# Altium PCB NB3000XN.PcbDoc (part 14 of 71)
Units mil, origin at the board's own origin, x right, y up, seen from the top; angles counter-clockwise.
Board outline 9527.56 x 6929.77 mil, 6 copper layers (Top Layer, GND+SHIELD, MidLayer1, MidLayer2, P2 - 3V3+5V0, Bottom Layer), stack 62.375 mil thick; 832 components, 1027 nets, 4655 pads, 4981 vias.
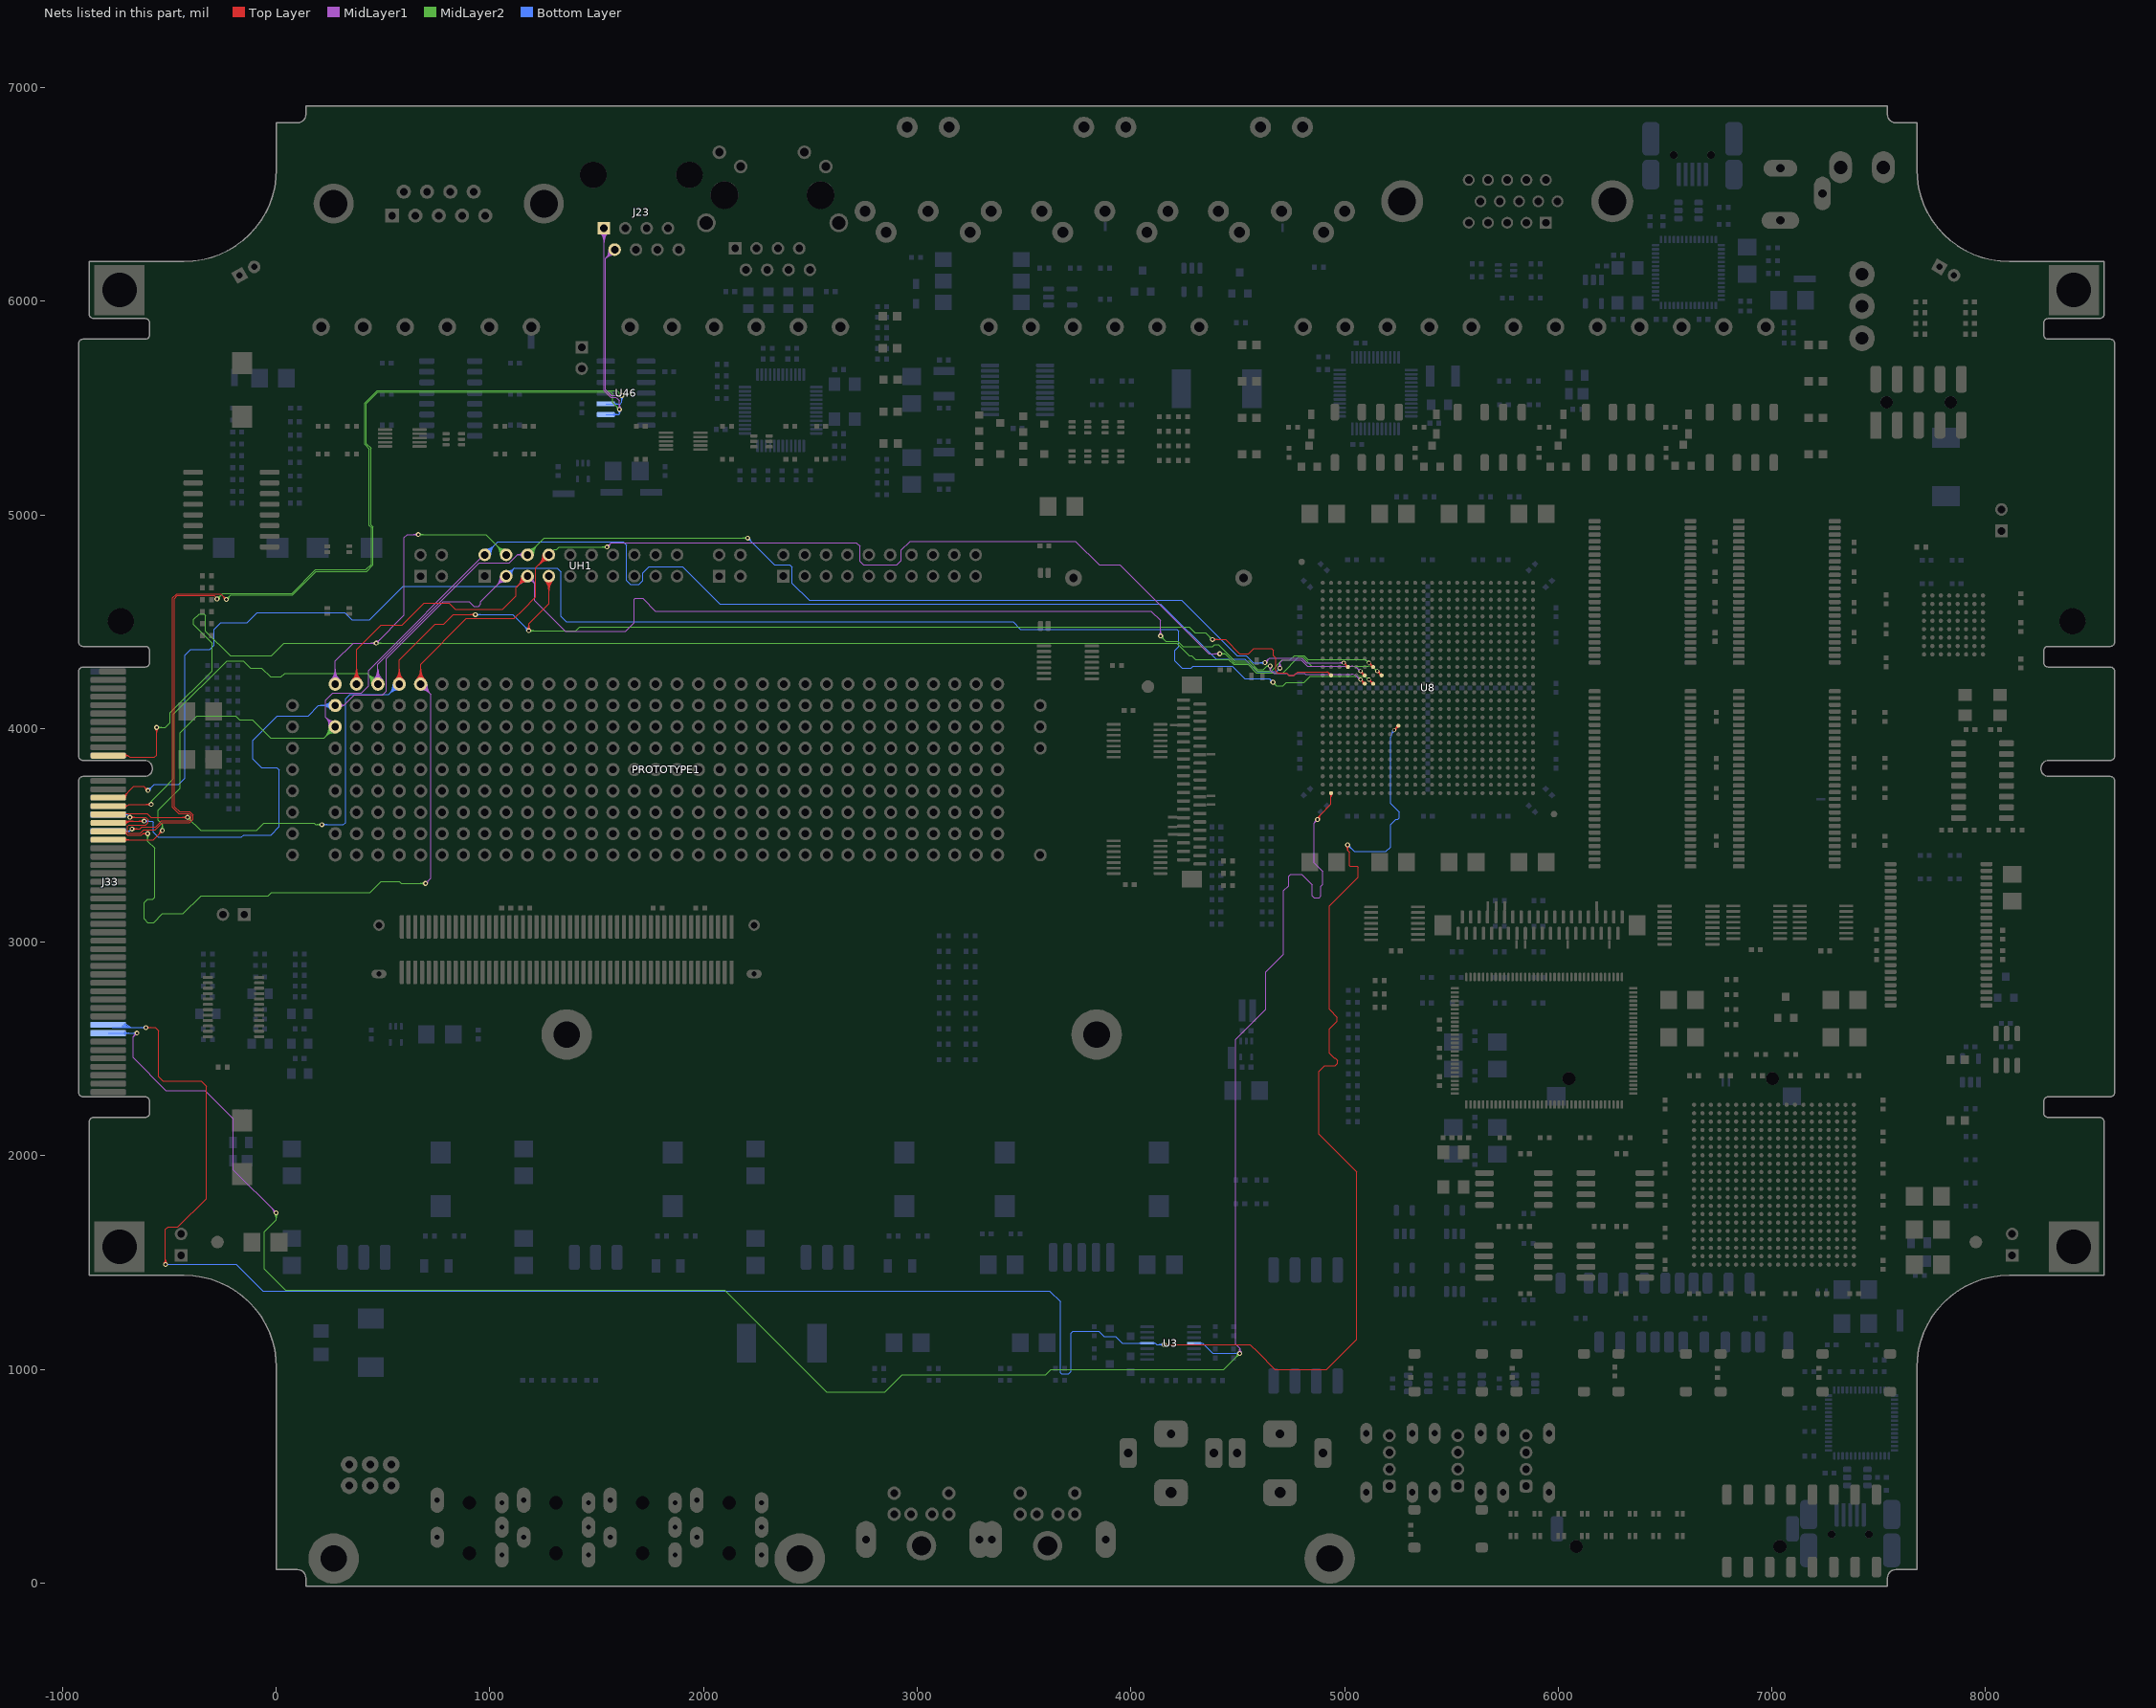
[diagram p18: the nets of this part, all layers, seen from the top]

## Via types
v1: diameter 23, hole 11.81, Top Layer to Bottom Layer, 3672 vias
v2: diameter 26, hole 11.81, Top Layer to Bottom Layer, 461 vias
v3: diameter 19, hole 11.81, Top Layer to Bottom Layer, tented both sides, 396 vias
v4: diameter 23.62, hole 11.81, Top Layer to Bottom Layer, 288 vias
v5: diameter 20, hole 11.81, Top Layer to Bottom Layer, 91 vias
v6: diameter 23, hole 11.81, Top Layer to Bottom Layer, tented both sides, 50 vias
v7: diameter 31, hole 11.81, Top Layer to Bottom Layer, 15 vias
v8: diameter 27.56, hole 11.81, Top Layer to Bottom Layer, tented both sides, 4 vias
v9: diameter 29, hole 11.81, Top Layer to Bottom Layer, 3 vias
v10: diameter 21, hole 11.81, Top Layer to Bottom Layer, 1 vias

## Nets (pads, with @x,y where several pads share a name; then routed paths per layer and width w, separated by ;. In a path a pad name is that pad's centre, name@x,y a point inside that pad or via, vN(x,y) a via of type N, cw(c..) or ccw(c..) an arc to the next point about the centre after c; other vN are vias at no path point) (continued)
ATE.RS485#.TX_N: J23.2 J33.B16 U46.10 | length 6293.5
  Top Layer w4: v4(-685,3585) -611.69,3585 -600.64,3573.96 -600.64,3559.46 -610.89,3549.21 -689.21,3549.21 -695,3543.42 -695,3515 -690,3510 -635,3510 -619.13,3525.87 -566.19,3525.87 -532.56,3559.5 -404.44,3559.5 -389.5,3574.44 -389.5,3595.56 -404.44,3610.5 -452.93,3610.5 -477,3634.57 -477,4607.75 -462.25,4622.5 -290,4622.5 -276.69,4609.19 v4(-276.69,4606.78) ; v4@-680.89,3580.89 cw(c-670.97,3570.97) -670.97,3585 cw(c-670.97,3599.03) v4@-680.89,3589.11 ; v4@-678.06,3578.06 cw(c-661.31,3561.31) -661.31,3585 cw(c-661.31,3608.69) v4@-678.06,3591.94
  MidLayer1 w4: J23.2@1556.57,6239.69 cw(c1506.43,6235.54) 1542,6199.96 ; J23.2@1560.55,6240.02 cw(c1517.7,6236.47) 1548.1,6206.07 cw(c1578.51,6175.66) J23.2@1582.06,6218.51 ; J23.2@1564.54,6240.35 cw(c1528.97,6237.4) 1554.21,6212.17 cw(c1579.44,6186.93) J23.2@1582.39,6222.5 ; J23.2@1568.53,6240.68 cw(c1540.24,6238.34) 1560.31,6218.27 cw(c1580.38,6198.2) J23.2@1582.72,6226.49 ; J23.2@1581.73,6214.53 ccw(c1577.58,6164.39) 1542,6199.96 ; J23.2@1584,6241.96 1542,6199.96 ; v1@1610.81,5552.66 ccw(c1594.59,5536.44) 1594.59,5559.37 ccw(c1594.59,5582.31) v1@1610.81,5566.09 ; v1@1613.64,5555.49 ccw(c1604.25,5546.1) 1604.25,5559.37 ccw(c1604.25,5572.65) v1@1613.64,5563.26 ; v1(1617.52,5559.37) 1568.84,5559.37 1542,5586.21 1542,6199.96
  MidLayer2 w4: v4(-276.69,4606.78) -250.1,4633.37 73.37,4633.37 184,4744 420.06,4744 445.5,4769.44 445.5,4940.56 436,4950.06 436,5309 414.19,5330.81 414.19,5524.19 465.98,5575.98 472.86,5582.86 1594.04,5582.86 v1(1617.52,5559.37) ; v4@-276.69,4612.59 ccw(c-276.69,4626.62) -266.77,4616.7 ccw(c-256.85,4606.78) v4@-270.88,4606.78 ; v4@-276.69,4616.59 ccw(c-276.69,4640.28) -259.94,4623.53 ccw(c-243.19,4606.78) v4@-266.88,4606.78 ; v1@1608.02,5559.37 ccw(c1585.09,5559.37) 1601.31,5575.59 ccw(c1617.52,5591.81) v1@1617.52,5568.87 ; v1@1612.02,5559.37 ccw(c1598.75,5559.37) 1608.14,5568.76 ccw(c1617.52,5578.15) v1@1617.52,5564.87
  Bottom Layer w4: J33.B16@-785.98,3597.74 -697.74,3597.74 ; J33.B16@-706.62,3592.34 cw(c-697.74,3587.75) -697.74,3597.74 ; J33.B16@-706.62,3603.15 ccw(c-697.74,3607.73) -697.74,3597.74 ; v4(-685,3585) -697.74,3597.74 ; U46.10@1542.57,5520.08 1610.08,5520.08 1617.52,5527.52 v1(1617.52,5559.37) ; U46.10@1578.17,5515.97 cw(c1588.09,5506.05) 1588.09,5520.08 cw(c1588.09,5534.11) U46.10@1578.17,5524.19 ; U46.10@1581,5513.14 cw(c1597.75,5496.39) 1597.75,5520.08 cw(c1597.75,5543.76) U46.10@1581,5527.01 ; v1@1610.81,5552.66 cw(c1594.59,5536.44) 1617.52,5536.44 cw(c1640.46,5536.44) v1@1624.24,5552.66 ; v1@1613.64,5555.49 cw(c1604.25,5546.1) 1617.52,5546.1 cw(c1630.8,5546.1) v1@1621.41,5555.49
ATE.RS485#.TX_P: J23.1 J33.B18 U46.9 | length 6345.3
  Top Layer w4: v1(-675,3530) -638.37,3530 -628.37,3540 -563.37,3540 -549.4,3553.98 -535.87,3567.5 -407.75,3567.5 -397.5,3577.75 -397.5,3592.25 -407.75,3602.5 -456.25,3602.5 -485,3631.25 -485,4611.06 -465.02,4631.04 -260.18,4631.04 v1(-233.51,4604.37) ; v1@-671.11,3526.11 cw(c-661.72,3516.72) -661.72,3530 cw(c-661.72,3543.28) v1@-671.11,3533.89 ; v1@-668.28,3523.28 cw(c-652.07,3507.06) -652.07,3530 cw(c-652.07,3552.93) v1@-668.28,3536.72 ; v1@-243.01,4604.37 ccw(c-265.95,4604.37) -249.73,4620.59 ccw(c-233.51,4636.81) v1@-233.51,4613.87 ; v1@-239.01,4604.37 ccw(c-252.29,4604.37) -242.9,4613.76 ccw(c-233.51,4623.15) v1@-233.51,4609.87
  MidLayer1 w4: J23.1@1514.54,6322.5 cw(c1467.54,6275.5) 1534,6275.5 cw(c1600.46,6275.5) J23.1@1553.46,6322.5 ; J23.1@1517.36,6325.32 cw(c1477.2,6285.16) 1534,6285.16 cw(c1590.8,6285.16) J23.1@1550.64,6325.32 ; J23.1@1520.19,6328.15 cw(c1486.86,6294.82) 1534,6294.82 cw(c1581.14,6294.82) J23.1@1547.81,6328.15 ; J23.1@1523.02,6330.98 cw(c1496.51,6304.47) 1534,6304.47 cw(c1571.49,6304.47) J23.1@1544.98,6330.98 ; J23.1@1534,6341.96 1534,5582.9 1565.52,5551.37 1590,5551.37 1606.86,5534.52 v1(1606.86,5494.04) ; v1@1600.14,5500.76 ccw(c1583.92,5516.98) 1606.86,5516.98 ccw(c1629.79,5516.98) v1@1613.57,5500.76 ; v1@1602.97,5497.93 ccw(c1593.58,5507.32) 1606.86,5507.32 ccw(c1620.14,5507.32) v1@1610.75,5497.93
  MidLayer2 w4: v1(-233.51,4604.37) -212.51,4625.37 76.68,4625.37 187.31,4736 423.37,4736 453.5,4766.13 453.5,4943.88 444,4953.38 444,5312.31 422.19,5334.12 422.19,5520.88 476.18,5574.86 1567.14,5574.86 1575,5567 1575,5525.9 v1(1606.86,5494.04) ; v1@-233.51,4609.87 ccw(c-233.51,4623.15) -224.12,4613.76 ccw(c-214.74,4604.37) v1@-228.01,4604.37 ; v1@-233.51,4613.87 ccw(c-233.51,4636.81) -217.3,4620.59 ccw(c-201.08,4604.37) v1@-224.01,4604.37 ; v1@1597.36,5494.04 ccw(c1574.42,5494.04) 1590.64,5510.26 ccw(c1606.86,5526.48) v1@1606.86,5503.54 ; v1@1601.36,5494.04 ccw(c1588.08,5494.04) 1597.47,5503.43 ccw(c1606.86,5512.82) v1@1606.86,5499.54
  Bottom Layer w4: J33.B18@-785.98,3519 -686,3519 v1(-675,3530) ; J33.B18@-711.58,3513.5 cw(c-698.3,3500.22) -698.3,3519 cw(c-698.3,3537.78) J33.B18@-711.58,3524.5 ; J33.B18@-708.76,3510.67 cw(c-688.65,3490.56) -688.65,3519 cw(c-688.65,3547.44) J33.B18@-708.76,3527.33 ; U46.9@1542.57,5470.08 1604.92,5470.08 1606.86,5472.01 ; U46.9@1578.17,5465.97 cw(c1588.09,5456.05) 1588.09,5470.08 cw(c1588.09,5484.11) U46.9@1578.17,5474.19 ; U46.9@1581,5463.14 cw(c1597.75,5446.39) 1597.75,5470.08 cw(c1597.75,5493.76) U46.9@1581,5477.01 ; v1@1600.34,5487.13 cw(c1586.07,5472.01) 1606.86,5472.01 ; v1@1603.08,5490.04 cw(c1594.82,5481.29) 1606.86,5481.29 cw(c1618.89,5481.29) v1@1610.63,5490.04 ; v1(1606.86,5494.04) 1606.86,5472.01 ; v1@1613.38,5487.13 ccw(c1627.64,5472.01) 1606.86,5472.01
ATE.SPDIF.IN: J33.B42 U3.4 U8.AF2 | length 10496.7
  Top Layer w4: v1(4873.52,3574.04) 4873.52,3582.37 4888.15,3597 4888.31,3597 4937.24,3645.93 4937.24,3655.26 4937.24,3660 4937.24,3670 U8.AF2@4937.24,3697.87 ; v1@4874.97,3574.43 cw(c4887.73,3577.89) 4878.38,3587.23 ; v1@4878.83,3575.48 cw(c4895.41,3579.97) 4883.27,3592.12 ; v1@4882.69,3576.53 cw(c4903.09,3582.05) 4888.15,3597 ; U8.AF2@4931.94,3692.57 cw(c4919.14,3679.77) 4937.24,3679.77 cw(c4955.35,3679.77) U8.AF2@4942.55,3692.57 ; U8.AF2@4932.05,3692.68 cw(c4919.52,3680.15) 4937.24,3680.15 cw(c4954.97,3680.15) U8.AF2@4942.44,3692.68
  MidLayer1 w4: v1@-660.98,2575.04 cw(c-683.91,2575.04) -667.69,2558.82 cw(c-651.48,2542.61) v1@-651.48,2565.54 ; v1@-656.98,2575.04 cw(c-670.25,2575.04) -660.86,2565.65 cw(c-651.48,2556.26) v1@-651.48,2569.54 ; v1(-651.48,2575.04) -668.98,2557.54 -668.98,2459.46 -515.73,2306.21 -332.28,2306.21 -200,2173.94 -200,1932.9 v1(-0.48,1733.37) ; v1@-9.98,1733.37 ccw(c-32.91,1733.37) -16.69,1749.59 ccw(c-0.48,1765.81) v1@-0.48,1742.87 ; v1@-5.98,1733.37 ccw(c-19.25,1733.37) -9.86,1742.76 ccw(c-0.48,1752.15) v1@-0.48,1738.87 ; v1@4503.12,1081.76 ccw(c4486.9,1097.98) 4509.84,1097.98 ccw(c4532.77,1097.98) v1@4516.56,1081.76 ; v1@4505.95,1078.93 ccw(c4496.56,1088.32) 4509.84,1088.32 ccw(c4523.12,1088.32) v1@4513.73,1078.93 ; v1(4509.84,1075.04) 4509.84,1098.39 4490.19,1118.04 4490.19,2544.69 4631.86,2686.36 4631.86,2861.36 4715.19,2944.69 4715.19,3240.71 4739.19,3264.71 4739.19,3308.71 4748.52,3318.04 4798.52,3318.04 4848.52,3268.04 4848.52,3216.71 4856.86,3208.37 4881.86,3208.37 4890.19,3216.71 4890.19,3262.04 4898.52,3270.37 4898.52,3331 4857.52,3372 4857.52,3558.04 ; v1@4864.02,3573.95 cw(c4841.83,3573.74) 4857.53,3558.04 ; v1@4868.02,3573.99 cw(c4855.18,3573.86) 4864.26,3564.78 cw(c4873.35,3555.69) v1@4873.47,3568.54 ; v1@4873.43,3564.54 ccw(c4873.22,3542.35) 4857.53,3558.04 ; v1(4873.52,3574.04) 4857.52,3558.04
  MidLayer2 w4: v1@-7.19,1726.66 cw(c-23.41,1710.44) -0.48,1710.44 cw(c22.46,1710.44) v1@6.24,1726.66 ; v1@-4.36,1729.49 cw(c-13.75,1720.1) -0.48,1720.1 cw(c12.8,1720.1) v1@3.41,1729.49 ; v1@-0.85,1733 v1(-0.48,1733.37) -0.48,1700 -55,1645.48 -55,1470.26 43.26,1372 2099.19,1372 2576.19,895 2850,895 2930,975 3601.46,975 3626.5,1000.04 4434.84,1000.04 v1(4509.84,1075.04) ; v1@4500.34,1075.04 cw(c4477.4,1075.04) 4493.62,1058.82 cw(c4509.84,1042.61) v1@4509.84,1065.54 ; v1@4504.34,1075.04 cw(c4491.06,1075.04) 4500.45,1065.65 cw(c4509.84,1056.26) v1@4509.84,1069.54
  Bottom Layer w4: J33.B42@-785.98,2574.12 -668.73,2574.12 -667.81,2575.04 ; J33.B42@-711.58,2568.62 cw(c-698.3,2555.34) -698.3,2574.12 cw(c-698.3,2592.9) J33.B42@-711.58,2579.62 ; J33.B42@-708.76,2565.79 cw(c-688.65,2545.68) -688.65,2574.12 cw(c-688.65,2602.56) J33.B42@-708.76,2582.45 ; v1@-659.73,2570.34 ccw(c-667.81,2565.75) -667.81,2575.04 ; v1@-659.73,2579.74 cw(c-667.81,2584.33) -667.81,2575.04 ; v1(-651.48,2575.04) -667.81,2575.04 ; U3.4@4295,1123.23 4335.34,1123.23 4383.52,1075.04 v1(4509.84,1075.04) ; U3.4@4324.31,1120.4 cw(c4331.14,1113.57) 4331.14,1123.23 cw(c4331.14,1132.89) U3.4@4324.31,1126.06 ; v1@4503.12,1068.32 ccw(c4486.9,1052.11) 4486.9,1075.04 ccw(c4486.9,1097.98) v1@4503.12,1081.76 ; v1@4505.95,1071.15 ccw(c4496.56,1061.76) 4496.56,1075.04 ccw(c4496.56,1088.32) v1@4505.95,1078.93
ATE.SPDIF.OUT: J33.B41 U3.11 U8.V10 | length 12149.4
  Top Layer w4: v1(-609.81,2600.04) -565,2600.04 -550,2585.04 -550,2370.18 -529.87,2350.04 -351.48,2350.04 -327.52,2326.08 -327.52,1799.35 -459.83,1667.04 -506.1,1667.04 -518.14,1655 v1(-518.14,1491.71) ; v1@-605.92,2596.15 cw(c-596.53,2586.76) -596.53,2600.04 cw(c-596.53,2613.32) v1@-605.92,2603.93 ; v1@-603.09,2593.32 cw(c-586.87,2577.11) -586.87,2600.04 cw(c-586.87,2622.98) v1@-603.09,2606.76 ; v1@-524.86,1498.43 ccw(c-541.08,1514.64) -518.14,1514.64 ccw(c-495.21,1514.64) v1@-511.43,1498.43 ; v1@-522.03,1495.6 ccw(c-531.42,1504.99) -518.14,1504.99 ccw(c-504.86,1504.99) v1@-514.25,1495.6 ; v1(4155,1116.71) 4558.29,1116.71 4592.79,1082.21 4674.96,1000.04 4915.19,1000.04 5056.86,1141.71 5056.86,1925.04 4880,2101.9 4880,2395 4907.5,2422.5 4957.25,2422.5 4967.5,2432.75 4967.5,2447.25 4957.25,2457.5 4952.75,2457.5 4930,2480.25 4930,2593.98 4966.02,2630 4966.02,2648.96 4929.5,2685.48 4929.5,3169.02 5064.19,3303.71 5064.19,3350.04 5058.52,3355.71 5026.19,3355.71 5023.52,3358.37 5023.52,3419.69 5014.52,3428.69 v1(5014.52,3455.71) ; v1@4158.89,1112.82 cw(c4168.28,1103.43) 4168.28,1116.71 cw(c4168.28,1129.99) v1@4158.89,1120.6 ; v1@4161.72,1109.99 cw(c4177.93,1093.77) 4177.93,1116.71 cw(c4177.93,1139.64) v1@4161.72,1123.43 ; v1@5007.81,3448.99 cw(c4991.59,3432.77) 5014.52,3432.77 cw(c5037.46,3432.77) v1@5021.24,3448.99 ; v1@5010.64,3451.82 cw(c5001.25,3442.43) 5014.52,3442.43 cw(c5027.8,3442.43) v1@5018.41,3451.82 ; v3(5232.52,3993.15) U8.V10@5252.2,4012.83 ; U8.V10@5244.7,4012.83 cw(c5226.6,4012.83) 5239.4,4000.03 cw(c5252.2,3987.23) U8.V10@5252.2,4005.33 ; U8.V10@5244.86,4012.83 cw(c5227.14,4012.83) 5239.67,4000.3 cw(c5252.2,3987.77) U8.V10@5252.2,4005.49 ; 5245.32,4005.95 cw(c5232.52,4018.76) 5232.52,4000.65 ccw(c5232.52,4018.76) 5245.32,4005.95 ; 5245.32,4005.95 ccw(c5258.13,3993.15) 5240.02,3993.15 cw(c5258.13,3993.15) 5245.32,4005.95
  Bottom Layer w4: J33.B41@-768.14,2600.04 v1(-609.81,2600.04) ; J33.B41@-722.9,2607.68 ccw(c-704.46,2626.12) J33.B41@-704.46,2600.04 ; J33.B41@-720.07,2610.51 ccw(c-694.8,2635.77) -694.8,2600.04 ; J33.B41@-717.24,2613.34 ccw(c-685.15,2645.43) -685.15,2600.04 ; J33.B41@-714.41,2616.16 ccw(c-675.49,2655.09) -675.49,2600.04 ; J33.B41@-711.58,2618.99 ccw(c-665.83,2664.74) -665.83,2600.04 ; J33.B41@-708.76,2621.82 ccw(c-656.17,2674.4) -656.17,2600.04 ; v1@-616.53,2593.32 ccw(c-632.74,2577.11) -632.74,2600.04 ccw(c-632.74,2622.98) v1@-616.53,2606.76 ; v1@-613.7,2596.15 ccw(c-623.09,2586.76) -623.09,2600.04 ccw(c-623.09,2613.32) v1@-613.7,2603.93 ; v1(-518.14,1491.71) -187.79,1491.71 -63.12,1367.04 3620,1367.04 3670,1317.04 3670,985 3675,980 3710,980 3720,990 3720,1170 3730,1180 3850,1180 3875,1155 3928.23,1155 3960,1123.23 U3.11@4076.5,1123.23 4115.19,1123.23 4115.19,1123.04 4121.52,1116.71 v1(4155,1116.71) ; U3.11@4047.19,1120.4 ccw(c4040.36,1113.57) 4040.36,1123.23 ccw(c4040.36,1132.88) U3.11@4047.19,1126.06 ; U3.11@4105.8,1120.4 cw(c4112.63,1113.57) 4112.63,1123.23 cw(c4112.63,1132.89) U3.11@4105.8,1126.06 ; v1@4148.28,1109.99 ccw(c4132.06,1093.77) 4132.06,1116.71 ccw(c4132.06,1139.64) v1@4148.28,1123.43 ; v1@4151.11,1112.82 ccw(c4141.72,1103.43) 4141.72,1116.71 ccw(c4141.72,1129.99) v1@4151.11,1120.6 ; v1@5014.52,3446.21 cw(c5014.52,3423.27) 5030.74,3439.49 cw(c5046.96,3455.71) v1@5024.02,3455.71 ; v1@5014.52,3450.21 cw(c5014.52,3436.93) 5023.91,3446.32 cw(c5033.3,3455.71) v1@5020.02,3455.71 ; v1(5014.52,3455.71) 5045.19,3425.04 5194.54,3425.04 5215.86,3446.35 5215.86,3550.9 5240,3575.04 5249.54,3575.04 5254.5,3580 5257.19,3582.69 5257.19,3609.86 5217.01,3650.04 5217.01,3655.26 5217.01,3660 5217.01,3670 5217.01,3876.1 5217.01,3960.47 cw(c5250.14,3960.64) 5222.1,3978.29 ; v3@5225.13,3991.85 cw(c5207.3,3988.7) 5222.13,3978.32 cw(c5236.97,3967.93) v3@5233.82,3985.76
ATE.UIO.IO0: J33.A19 PROTOTYPE1.B1 U8.M6 UH1.2 | length 8859.2
  Top Layer w4: J33.A19@-785.98,3479.63 -575.55,3479.63 v1(-532.81,3522.37) ; J33.A19@-711.58,3474.13 cw(c-698.3,3460.85) -698.3,3479.63 cw(c-698.3,3498.41) J33.A19@-711.58,3485.13 ; J33.A19@-708.76,3471.3 cw(c-688.65,3451.19) -688.65,3479.63 cw(c-688.65,3508.07) J33.A19@-708.76,3487.96 ; v1@-542.31,3522.37 cw(c-565.24,3522.37) -549.03,3506.16 cw(c-532.81,3489.94) v1@-532.81,3512.87 ; v1@-538.31,3522.37 cw(c-551.59,3522.37) -542.2,3512.99 cw(c-532.81,3503.6) v1@-532.81,3516.87 ; v3(5075.04,4268.74) U8.M6@5094.72,4249.06 ; U8.M6@5087.22,4249.06 ccw(c5069.12,4249.06) 5081.92,4261.86 ccw(c5094.72,4274.66) U8.M6@5094.72,4256.56 ; U8.M6@5087.38,4249.06 ccw(c5069.66,4249.06) 5082.19,4261.59 ccw(c5094.72,4274.12) U8.M6@5094.72,4256.4 ; 5087.84,4255.94 cw(c5100.65,4268.74) 5082.54,4268.74 ccw(c5100.65,4268.74) 5087.84,4255.94 ; 5087.84,4255.94 ccw(c5075.04,4243.13) 5075.04,4261.24 cw(c5075.04,4243.13) 5087.84,4255.94
  MidLayer1 w4: PROTOTYPE1.B1@247.22,4010.62 ccw(c194.34,4014.98) 231.86,4052.5 ; PROTOTYPE1.B1@251.21,4010.29 ccw(c205.62,4014.05) 237.96,4046.39 ccw(c270.3,4078.73) PROTOTYPE1.B1@274.07,4033.15 ; PROTOTYPE1.B1@255.19,4009.96 ccw(c216.9,4013.12) 244.07,4040.29 ccw(c271.24,4067.45) PROTOTYPE1.B1@274.39,4029.16 ; PROTOTYPE1.B1@259.18,4009.63 ccw(c228.18,4012.19) 250.17,4034.18 ccw(c272.17,4056.17) PROTOTYPE1.B1@274.72,4025.18 ; PROTOTYPE1.B1@273.74,4037.14 cw(c269.37,4090.01) 231.86,4052.5 ; PROTOTYPE1.B1@276.12,4008.23 231.86,4052.5 ; UH1.2@976.12,4813.23 973.23,4813.23 431.86,4271.86 431.86,4200.04 398.52,4166.71 265.19,4166.71 231.86,4133.37 231.86,4052.5 ; v1@4690.81,4289.09 ccw(c4674.59,4305.31) 4697.52,4305.31 ccw(c4720.46,4305.31) v1@4704.24,4289.09 ; v1@4693.64,4286.26 ccw(c4684.25,4295.65) 4697.52,4295.65 ccw(c4710.8,4295.65) v1@4701.41,4286.26 ; v1(4697.52,4282.37) 4697.52,4307.52 4710,4320 4798,4320 4825.4,4292.6 4855.26,4292.6 4860,4292.6 4870,4292.6 4918.62,4292.6 4938.04,4292.6 5012.16,4292.6 ; 4998.23,4292.6 5012.16,4292.6 ; v3@5067.57,4268.09 ccw(c5049.53,4266.51) 5061.17,4280.38 ; v3@5074.39,4276.21 cw(c5072.81,4294.25) 5061.17,4280.38 ; 5012.16,4292.6 5031.66,4292.6 cw(c5031.66,4250.87) 5061.17,4280.38
  MidLayer2 w4: v1@-539.53,3529.09 ccw(c-555.74,3545.31) -532.81,3545.31 ccw(c-509.87,3545.31) v1@-526.09,3529.09 ; v1@-536.7,3526.26 ccw(c-546.09,3535.65) -532.81,3535.65 ccw(c-519.53,3535.65) v1@-528.92,3526.26 ; v1(-532.81,3522.37) -532.81,3550.5 -552.31,3570 -552.31,3617.32 -500.71,3668.93 -449,3720.63 -449,3979.89 -430.84,3998.05 -370.51,4058.37 -189.77,4058.37 -172.9,4041.5 -111.5,4041.5 -90.78,4020.78 -25.87,3955.87 223.76,3955.87 PROTOTYPE1.B1@276.12,4008.23 ; PROTOTYPE1.B1@247.12,4008.23 cw(c177.11,4008.23) 226.62,3958.73 cw(c276.12,3909.22) PROTOTYPE1.B1@276.12,3979.23 ; PROTOTYPE1.B1@251.12,4008.23 cw(c190.77,4008.23) 233.44,3965.56 cw(c276.12,3922.88) PROTOTYPE1.B1@276.12,3983.23 ; PROTOTYPE1.B1@255.12,4008.23 cw(c204.42,4008.23) 240.27,3972.39 cw(c276.12,3936.54) PROTOTYPE1.B1@276.12,3987.23 ; PROTOTYPE1.B1@259.12,4008.23 cw(c218.08,4008.23) 247.1,3979.21 cw(c276.12,3950.19) PROTOTYPE1.B1@276.12,3991.23 ; PROTOTYPE1.B1@263.12,4008.23 cw(c231.74,4008.23) 253.93,3986.04 cw(c276.12,3963.85) PROTOTYPE1.B1@276.12,3995.23
  Bottom Layer w4: UH1.2@976.12,4813.23 1037.93,4875.04 1623.52,4875.04 1640.19,4858.37 1640.19,4691.71 1656.86,4675.04 1698.52,4675.04 1715.19,4691.71 1715.19,4728.02 1745.54,4758.37 1901.63,4758.37 2076.29,4583.71 4139.86,4583.71 4398.52,4325.04 4534.17,4325.04 4592.17,4267.04 4682.19,4267.04 v1(4697.52,4282.37) ; UH1.2@976.12,4828.76 ccw(c976.12,4866.25) 1002.63,4839.74 ccw(c1029.14,4813.23) UH1.2@991.65,4813.23 ; UH1.2@976.12,4832.76 ccw(c976.12,4879.91) 1009.46,4846.57 ccw(c1042.79,4813.23) UH1.2@995.65,4813.23 ; UH1.2@976.12,4836.76 ccw(c976.12,4893.56) 1016.29,4853.4 ccw(c1056.45,4813.23) UH1.2@999.65,4813.23 ; UH1.2@976.12,4840.76 ccw(c976.12,4907.22) 1023.11,4860.23 ccw(c1070.11,4813.23) UH1.2@1003.65,4813.23
ATE.UIO.IO1: J33.A17 PROTOTYPE1.A1 U8.N7 UH1.3 | length 9008.5
  Top Layer w4: J33.A17@-785.98,3558.37 -777.65,3566.71 v1(-618.14,3566.71) ; J33.A17@-717.24,3558.53 cw(c-697.49,3538.78) -697.49,3566.71 ; J33.A17@-714.41,3555.7 cw(c-687.84,3529.13) -687.84,3566.71 ; J33.A17@-711.58,3552.87 cw(c-678.18,3519.47) -678.18,3566.71 ; J33.A17@-708.76,3550.04 cw(c-668.52,3509.81) -668.52,3566.71 ; v1@-624.86,3559.99 ccw(c-641.08,3543.77) -641.08,3566.71 ccw(c-641.08,3589.64) v1@-624.86,3573.43 ; v1@-622.03,3562.82 ccw(c-631.42,3553.43) -631.42,3566.71 ccw(c-631.42,3579.99) v1@-622.03,3570.6 ; v3(5114.41,4229.37) U8.N7@5134.09,4209.69 ; U8.N7@5126.59,4209.69 ccw(c5108.49,4209.69) 5121.29,4222.49 ccw(c5134.09,4235.29) U8.N7@5134.09,4217.19 ; U8.N7@5126.75,4209.69 ccw(c5109.03,4209.69) 5121.56,4222.22 ccw(c5134.09,4234.75) U8.N7@5134.09,4217.03 ; 5127.21,4216.57 ccw(c5114.41,4203.76) 5114.41,4221.87 cw(c5114.41,4203.76) 5127.21,4216.57 ; 5127.21,4216.57 cw(c5140.02,4229.37) 5121.91,4229.37 ccw(c5140.02,4229.37) 5127.21,4216.57
  MidLayer1 w4: PROTOTYPE1.A1@276.12,4108.23 315.19,4108.23 ; PROTOTYPE1.A1@300.05,4101 cw(c309.8,4098.05) 309.8,4108.23 cw(c309.8,4118.42) PROTOTYPE1.A1@300.05,4115.47 ; PROTOTYPE1.A1@303.88,4099.84 cw(c315.19,4096.42) 315.19,4108.23 ; PROTOTYPE1.A1@303.88,4116.63 ccw(c315.19,4120.05) 315.19,4108.23 ; UH1.3@1048.59,4713.23 cw(c982.14,4713.23) 1029.13,4666.24 cw(c1076.12,4619.25) UH1.3@1076.12,4685.71 ; UH1.3@1052.59,4713.23 cw(c995.79,4713.23) 1035.96,4673.07 cw(c1076.12,4632.91) UH1.3@1076.12,4689.71 ; UH1.3@1056.59,4713.23 cw(c1009.45,4713.23) 1042.79,4679.9 cw(c1076.12,4646.56) UH1.3@1076.12,4693.71 ; UH1.3@1060.59,4713.23 cw(c1023.11,4713.23) 1049.61,4686.73 cw(c1076.12,4660.22) UH1.3@1076.12,4697.71 ; UH1.3@1076.12,4713.23 957.5,4594.61 957.5,4582.75 947.25,4572.5 925,4572.5 902.5,4595 782.13,4595 515.19,4328.06 515.19,4275 515.19,4175.04 498.52,4158.37 365.33,4158.37 315.19,4108.23
  MidLayer2 w4: v1(4665.19,4216.71) 4681.19,4200.71 ; v1@4665.24,4211.21 cw(c4665.37,4198.36) 4674.45,4207.45 cw(c4683.54,4216.53) v1@4670.69,4216.65 ; v1@4665.28,4207.21 cw(c4665.5,4185.01) 4681.19,4200.71 ; v1@4674.69,4216.62 ccw(c4696.88,4216.4) 4681.19,4200.71 ; 5100.83,4240.76 ccw(c5090.9,4230.83) 5090.9,4244.88 4997.36,4244.88 4870,4244.88 4860,4244.88 4855.26,4244.88 4839.86,4244.88 4811.69,4216.71 4728.86,4216.71 4712.86,4200.71 4681.19,4200.71 ; v3@5106.94,4228.72 ccw(c5088.9,4227.14) 5100.54,4241.01 ccw(c5112.18,4254.88) v3@5113.76,4236.84
  Bottom Layer w4: v1(-618.14,3566.71) -580,3566.71 -575,3561.71 -575,3515 -553,3493 -162,3493 -152.79,3502.21 -24.11,3502.21 15,3541.31 15,3805.59 3.88,3816.71 -68.14,3816.71 -100.64,3849.2 -109.51,3858.07 -109.51,3945.49 5,4060 150,4060 198.23,4108.23 PROTOTYPE1.A1@276.12,4108.23 ; v1@-614.25,3562.82 cw(c-604.86,3553.43) -604.86,3566.71 cw(c-604.86,3579.99) v1@-614.25,3570.6 ; v1@-611.43,3559.99 cw(c-595.21,3543.77) -595.21,3566.71 cw(c-595.21,3589.64) v1@-611.43,3573.43 ; PROTOTYPE1.A1@255.62,4087.73 ccw(c206.11,4038.22) 206.11,4108.23 ccw(c206.11,4178.25) PROTOTYPE1.A1@255.62,4128.74 ; PROTOTYPE1.A1@258.44,4090.56 ccw(c215.77,4047.88) 215.77,4108.23 ccw(c215.77,4168.59) PROTOTYPE1.A1@258.44,4125.91 ; PROTOTYPE1.A1@261.27,4093.39 ccw(c225.42,4057.54) 225.42,4108.23 ccw(c225.42,4158.93) PROTOTYPE1.A1@261.27,4123.08 ; PROTOTYPE1.A1@264.1,4096.21 ccw(c235.08,4067.19) 235.08,4108.23 ccw(c235.08,4149.28) PROTOTYPE1.A1@264.1,4120.26 ; PROTOTYPE1.A1@266.93,4099.04 ccw(c244.74,4076.85) 244.74,4108.23 ccw(c244.74,4139.62) PROTOTYPE1.A1@266.93,4117.43 ; UH1.3@1076.12,4713.23 1112.93,4750.04 ; UH1.3@1079.76,4732.42 ccw(c1084.45,4757.12) 1102.23,4739.34 ccw(c1120.01,4721.56) UH1.3@1095.31,4716.88 ; UH1.3@1080.51,4736.35 ccw(c1086.16,4766.11) 1107.58,4744.69 ccw(c1129,4723.27) UH1.3@1099.24,4717.62 ; UH1.3@1081.25,4740.28 ccw(c1087.86,4775.1) 1112.93,4750.04 ; UH1.3@1103.17,4718.37 cw(c1137.99,4724.98) 1112.93,4750.04 ; v1@4655.69,4216.71 ccw(c4632.76,4216.71) 4648.97,4232.93 ccw(c4665.19,4249.14) v1@4665.19,4226.21 ; v1@4659.69,4216.71 ccw(c4646.41,4216.71) 4655.8,4226.1 ccw(c4665.19,4235.49) v1@4665.19,4222.21 ; v1(4665.19,4216.71) 4647.19,4234.71 4532.19,4234.71 4475.19,4291.71 4290.19,4291.71 4281.86,4283.37 4240.19,4283.37 4206.86,4316.71 4206.86,4365 4225,4383.14 4225,4455 4215,4465 3483.56,4465 3448.19,4500.37 1356.48,4500.37 1331.86,4525 1331.86,4733.37 1315.19,4750.04 1112.93,4750.04
ATE.UIO.IO2: J33.A11 PROTOTYPE1.H1 U8.M8 UH1.4 | length 9639.4
  Top Layer w4: J33.A11@-785.98,3873.33 -692.96,3873.33 ; J33.A11@-710.95,3868.55 cw(c-701.15,3860.91) -701.15,3873.33 cw(c-701.15,3885.76) J33.A11@-710.95,3878.12 ; J33.A11@-707.8,3866.09 cw(c-692.96,3854.52) -692.96,3873.33 ; J33.A11@-707.8,3880.58 ccw(c-692.96,3892.15) -692.96,3873.33 ; v1@-566.72,3998.28 cw(c-582.94,3982.06) -560,3982.06 cw(c-537.07,3982.06) v1@-553.28,3998.28 ; v1@-563.89,4001.11 cw(c-573.28,3991.72) -560,3991.72 cw(c-546.72,3991.72) v1@-556.11,4001.11 ; v1(-560,4005) -560,3875 -569.63,3865.37 -685,3865.37 -692.96,3873.33 ; v3(5153.78,4268.74) U8.M8@5173.46,4249.06 ; U8.M8@5165.96,4249.06 ccw(c5147.86,4249.06) 5160.66,4261.86 ccw(c5173.46,4274.66) U8.M8@5173.46,4256.56 ; U8.M8@5166.12,4249.06 ccw(c5148.4,4249.06) 5160.93,4261.59 ccw(c5173.46,4274.12) U8.M8@5173.46,4256.4 ; 5166.58,4255.94 cw(c5179.39,4268.74) 5161.28,4268.74 ccw(c5179.39,4268.74) 5166.58,4255.94 ; 5166.58,4255.94 ccw(c5153.78,4243.13) 5153.78,4261.24 cw(c5153.78,4243.13) 5166.58,4255.94
  MidLayer1 w4: PROTOTYPE1.H1@255.62,4228.74 ccw(c206.11,4278.25) 276.12,4278.25 ccw(c346.13,4278.25) PROTOTYPE1.H1@296.63,4228.74 ; PROTOTYPE1.H1@258.44,4225.91 ccw(c215.77,4268.59) 276.12,4268.59 ccw(c336.48,4268.59) PROTOTYPE1.H1@293.8,4225.91 ; PROTOTYPE1.H1@261.27,4223.08 ccw(c225.42,4258.93) 276.12,4258.93 ccw(c326.82,4258.93) PROTOTYPE1.H1@290.97,4223.08 ; PROTOTYPE1.H1@264.1,4220.26 ccw(c235.08,4249.28) 276.12,4249.28 ccw(c317.16,4249.28) PROTOTYPE1.H1@288.14,4220.26 ; PROTOTYPE1.H1@266.93,4217.43 ccw(c244.74,4239.62) 276.12,4239.62 ccw(c307.51,4239.62) PROTOTYPE1.H1@285.31,4217.43 ; v1@461.14,4393.32 ccw(c444.92,4377.11) 444.92,4400.04 ccw(c444.92,4422.98) v1@461.14,4406.76 ; v1@463.97,4396.15 ccw(c454.58,4386.76) 454.58,4400.04 ccw(c454.58,4413.32) v1@463.97,4403.93 ; v1@467.86,4405.54 ccw(c467.86,4418.82) 477.25,4409.43 ccw(c486.64,4400.04) v1@473.36,4400.04 ; v1@467.86,4409.54 ccw(c467.86,4432.48) 484.07,4416.26 ccw(c500.29,4400.04) v1@477.36,4400.04 ; v1@658.47,4901.66 ccw(c642.26,4885.44) 642.26,4908.37 ccw(c642.26,4931.31) v1@658.47,4915.09 ; v1@661.3,4904.49 ccw(c651.91,4895.1) 651.91,4908.37 ccw(c651.91,4921.65) v1@661.3,4912.26 ; v1(665.19,4908.37) 613.37,4908.37 598.52,4893.52 598.52,4530.71 v1(467.86,4400.04) 360.04,4400.04 276.12,4316.12 PROTOTYPE1.H1@276.12,4208.23 ; PROTOTYPE1.H1@276.12,4208.23 PROTOTYPE1.H1@276.12,4208.23 PROTOTYPE1.H1@276.12,4208.23
  MidLayer2 w4: v1(-560,4005) -520,4005 -497,4028 -497,4073.65 -300.14,4270.51 -300.14,4400.04 -382,4481.9 -386,4485.89 -386,4511.19 -360.31,4536.87 -338.31,4536.87 -330,4528.56 -330,4455.88 -215.5,4341.37 -22.21,4341.37 36.46,4400.04 v1(467.86,4400.04) 4215.19,4400.04 4273.52,4341.71 4284.5,4341.71 4302.17,4324.04 4345,4324.04 4456.86,4324.04 4480.86,4300.04 4548.52,4300.04 4587.52,4261.04 4712.19,4261.04 4784.52,4333.37 4806.49,4333.37 4847.26,4292.6 4855.26,4292.6 4860,4292.6 4870,4292.6 4997.36,4292.6 5016.78,4292.6 5090.9,4292.6 5110.4,4292.6 cw(c5110.4,4250.87) 5139.91,4280.38 ; v1@-556.11,4001.11 cw(c-546.72,3991.72) -546.72,4005 cw(c-546.72,4018.28) v1@-556.11,4008.89 ; v1@-553.28,3998.28 cw(c-537.07,3982.06) -537.07,4005 cw(c-537.07,4027.93) v1@-553.28,4011.72 ; v1@461.14,4393.32 ccw(c444.92,4377.11) 444.92,4400.04 ccw(c444.92,4422.98) v1@461.14,4406.76 ; v1@463.97,4396.15 ccw(c454.58,4386.76) 454.58,4400.04 ccw(c454.58,4413.32) v1@463.97,4403.93 ; v1@471.75,4396.15 cw(c481.14,4386.76) 481.14,4400.04 cw(c481.14,4413.32) v1@471.75,4403.93 ; v1@474.57,4393.32 cw(c490.79,4377.11) 490.79,4400.04 cw(c490.79,4422.98) v1@474.57,4406.76 ; v1(665.19,4908.37) 980.98,4908.37 UH1.4@1076.12,4813.23 ; v1@669.08,4904.49 cw(c678.47,4895.1) 678.47,4908.37 cw(c678.47,4921.65) v1@669.08,4912.26 ; v1@671.91,4901.66 cw(c688.13,4885.44) 688.13,4908.37 cw(c688.13,4931.31) v1@671.91,4915.09 ; UH1.4@1048.59,4813.23 ccw(c982.14,4813.23) 1029.13,4860.23 ccw(c1076.12,4907.22) UH1.4@1076.12,4840.76 ; UH1.4@1052.59,4813.23 ccw(c995.79,4813.23) 1035.96,4853.4 ccw(c1076.12,4893.56) UH1.4@1076.12,4836.76 ; UH1.4@1056.59,4813.23 ccw(c1009.45,4813.23) 1042.79,4846.57 ccw(c1076.12,4879.91) UH1.4@1076.12,4832.76 ; UH1.4@1060.59,4813.23 ccw(c1023.11,4813.23) 1049.61,4839.74 ccw(c1076.12,4866.25) UH1.4@1076.12,4828.76 ; v3@5146.31,4268.09 ccw(c5128.27,4266.51) 5139.91,4280.38 ; v3@5153.13,4276.21 cw(c5151.55,4294.25) 5139.91,4280.38
ATE.UIO.IO3: J33.A14 PROTOTYPE1.H2 U8.N6 UH1.5 | length 10092.4
  Top Layer w4: J33.A14@-785.98,3676.48 -718.52,3676.48 -666,3729 -619,3729 v1(-600,3710) ; J33.A14@-717.08,3684.26 ccw(c-717.08,3699.59) J33.A14@-706.25,3688.75 ; J33.A14@-717.08,3688.26 ccw(c-717.08,3713.24) -699.42,3695.58 ; J33.A14@-709.3,3676.48 cw(c-687.07,3676.48) -702.79,3692.21 ; J33.A14@-705.3,3676.48 cw(c-673.41,3676.48) -695.96,3699.04 ; v1@-609.5,3710 ccw(c-632.44,3710) -616.22,3726.22 ccw(c-600,3742.43) v1@-600,3719.5 ; v1@-605.5,3710 ccw(c-618.78,3710) -609.39,3719.39 ccw(c-600,3728.78) v1@-600,3715.5 ; PROTOTYPE1.H2@355.62,4228.74 ccw(c306.11,4278.25) 376.12,4278.25 ccw(c446.13,4278.25) PROTOTYPE1.H2@396.63,4228.74 ; PROTOTYPE1.H2@358.44,4225.91 ccw(c315.77,4268.59) 376.12,4268.59 ccw(c436.48,4268.59) PROTOTYPE1.H2@393.8,4225.91 ; PROTOTYPE1.H2@361.27,4223.08 ccw(c325.42,4258.93) 376.12,4258.93 ccw(c426.82,4258.93) PROTOTYPE1.H2@390.97,4223.08 ; PROTOTYPE1.H2@364.1,4220.26 ccw(c335.08,4249.28) 376.12,4249.28 ccw(c417.16,4249.28) PROTOTYPE1.H2@388.14,4220.26 ; PROTOTYPE1.H2@366.93,4217.43 ccw(c344.74,4239.62) 376.12,4239.62 ccw(c407.51,4239.62) PROTOTYPE1.H2@385.31,4217.43 ; PROTOTYPE1.H2@376.12,4208.23 376.12,4369.81 490.02,4483.71 588.71,4483.71 692.81,4587.81 808.38,4587.81 837.81,4558.37 1059.84,4558.37 1123.52,4622.06 1123.52,4660.64 UH1.5@1176.12,4713.23 ; UH1.5@1148.59,4713.23 cw(c1082.14,4713.23) 1129.13,4666.24 cw(c1176.12,4619.25) UH1.5@1176.12,4685.71 ; UH1.5@1152.59,4713.23 cw(c1095.79,4713.23) 1135.96,4673.07 cw(c1176.12,4632.91) UH1.5@1176.12,4689.71 ; UH1.5@1156.59,4713.23 cw(c1109.45,4713.23) 1142.79,4679.9 cw(c1176.12,4646.56) UH1.5@1176.12,4693.71 ; UH1.5@1160.59,4713.23 cw(c1123.11,4713.23) 1149.61,4686.73 cw(c1176.12,4660.22) UH1.5@1176.12,4697.71 ; v3(5075.04,4229.37) U8.N6@5094.72,4209.69 ; U8.N6@5087.22,4209.69 ccw(c5069.12,4209.69) 5081.92,4222.49 ccw(c5094.72,4235.29) U8.N6@5094.72,4217.19 ; U8.N6@5087.38,4209.69 ccw(c5069.66,4209.69) 5082.19,4222.22 ccw(c5094.72,4234.75) U8.N6@5094.72,4217.03 ; 5087.84,4216.57 cw(c5100.65,4229.37) 5082.54,4229.37 ccw(c5100.65,4229.37) 5087.84,4216.57 ; 5087.84,4216.57 ccw(c5075.04,4203.76) 5075.04,4221.87 cw(c5075.04,4203.76) 5087.84,4216.57
  MidLayer1 w4: UH1.5@1176.12,4713.23 1210,4679.36 1210,4598.19 1352.19,4456 1636,4456 1675,4495 1675,4605 1680,4610 1715,4610 1774.96,4550.04 4094.96,4550.04 4138.86,4506.14 v1(4138.86,4433.37) ; UH1.5@1181.1,4694.35 cw(c1186.14,4675.19) 1200.15,4689.2 cw(c1214.16,4703.21) UH1.5@1195,4708.26 ; UH1.5@1182.12,4690.48 cw(c1188.2,4667.4) 1205.08,4684.28 cw(c1221.95,4701.16) UH1.5@1198.87,4707.24 ; UH1.5@1183.13,4686.62 cw(c1190.25,4659.61) 1210,4679.36 cw(c1229.75,4699.11) UH1.5@1202.74,4706.22 ; v1@4132.14,4440.09 ccw(c4115.92,4456.31) 4138.86,4456.31 ccw(c4161.79,4456.31) v1@4145.57,4440.09 ; v1@4134.97,4437.26 ccw(c4125.58,4446.65) 4138.86,4446.65 ccw(c4152.14,4446.65) v1@4142.75,4437.26 ; v1@4647.29,4284.78 cw(c4640.85,4275.04) 4652.52,4275.04 ; v1(4652.52,4292.71) 4652.52,4275.04 ; v1@4657.76,4284.78 ccw(c4664.2,4275.04) 4652.52,4275.04 ; 4998.23,4253.23 5012.16,4253.23 ; v3@5067.57,4228.72 ccw(c5049.53,4227.14) 5061.17,4241.01 ; v3@5074.39,4236.84 cw(c5072.81,4254.88) 5061.17,4241.01 ; 4652.52,4275.04 4669.19,4258.37 4730.52,4258.37 4740.19,4248.71 4763.86,4248.71 4773.52,4258.37 4812,4258.37 4817.14,4253.23 4860,4253.23 4870,4253.23 4918.62,4253.23 4938.04,4253.23 5012.16,4253.23 ; 5012.16,4253.23 5031.66,4253.23 cw(c5031.66,4211.5) 5061.17,4241.01
  MidLayer2 w4: v1@4138.86,4423.87 cw(c4138.86,4400.94) 4155.07,4417.16 cw(c4171.29,4433.37) v1@4148.36,4433.37 ; v1@4138.86,4427.87 cw(c4138.86,4414.6) 4148.25,4423.99 cw(c4157.64,4433.37) v1@4144.36,4433.37 ; v1(4138.86,4433.37) 4164.19,4408.04 4218.71,4408.04 4243.37,4383.37 4383.15,4383.37 4392.62,4392.85 4410.67,4392.85 4487.15,4316.37 4554.82,4316.37 4594.15,4277.04 4619.65,4277.04 4635.32,4292.71 ; v1@4644.48,4287.65 ccw(c4635.32,4281.88) 4635.32,4292.71 ; v1@4644.48,4297.77 cw(c4635.32,4303.53) 4635.32,4292.71 ; v1(4652.52,4292.71) 4635.32,4292.71
  Bottom Layer w4: v1(-600,3710) -570.78,3739.22 -455.78,3739.22 -427,3768 -427,4343 -400,4370 -310,4370 -290,4390 -290,4465 -260,4495 -135,4495 -88.29,4541.71 321.67,4541.71 355,4508.37 436.15,4508.37 594.48,4666.71 1129.59,4666.71 ; v1@-600,3715.5 ccw(c-600,3728.78) -590.61,3719.39 ccw(c-581.22,3710) v1@-594.5,3710 ; v1@-600,3719.5 ccw(c-600,3742.43) -583.78,3726.22 ccw(c-567.57,3710) v1@-590.5,3710 ; UH1.5@1148.59,4713.04 cw(c1083.73,4712.58) 1129.6,4666.71 ; UH1.5@1152.59,4713.07 cw(c1097.15,4712.67) 1136.36,4673.47 cw(c1175.56,4634.27) UH1.5@1175.95,4689.71 ; UH1.5@1156.59,4713.1 cw(c1110.58,4712.77) 1143.12,4680.23 cw(c1175.66,4647.69) UH1.5@1175.98,4693.71 ; UH1.5@1160.59,4713.12 cw(c1124.01,4712.86) 1149.88,4686.99 cw(c1175.75,4661.12) UH1.5@1176.01,4697.71 ; UH1.5@1175.93,4685.71 ccw(c1175.46,4620.84) 1129.6,4666.71 ; UH1.5@1176.12,4713.23 1129.59,4666.71
ATE.UIO.IO4: J33.A15 PROTOTYPE1.H3 U8.L4 UH1.6 | length 8723.9
  Top Layer w4: J33.A15@-785.98,3637.11 -697.93,3637.11 ; J33.A15@-706.57,3631.8 cw(c-697.93,3627.43) -697.93,3637.11 ; J33.A15@-706.57,3642.43 ccw(c-697.93,3646.8) -697.93,3637.11 ; v1@-591.72,3638.28 ccw(c-607.94,3622.06) -607.94,3645 ccw(c-607.94,3667.93) v1@-591.72,3651.72 ; v1@-588.89,3641.11 ccw(c-598.28,3631.72) -598.28,3645 ccw(c-598.28,3658.28) v1@-588.89,3648.89 ; v1(-585,3645) -690.04,3645 -691.7,3643.34 -697.93,3637.11 ; v3(4996.3,4308.11) U8.L4@5015.98,4288.43 ; U8.L4@5008.48,4288.43 ccw(c4990.38,4288.43) 5003.18,4301.23 ccw(c5015.98,4314.03) U8.L4@5015.98,4295.93 ; U8.L4@5008.64,4288.43 ccw(c4990.92,4288.43) 5003.45,4300.96 ccw(c5015.98,4313.49) U8.L4@5015.98,4295.77 ; 5009.1,4295.31 cw(c5021.91,4308.11) 5003.8,4308.11 ccw(c5021.91,4308.11) 5009.1,4295.31 ; 5009.1,4295.31 ccw(c4996.3,4282.5) 4996.3,4300.61 cw(c4996.3,4282.5) 5009.1,4295.31
  MidLayer1 w4: PROTOTYPE1.H3@455.62,4228.74 ccw(c406.11,4278.25) 476.12,4278.25 ccw(c546.13,4278.25) PROTOTYPE1.H3@496.63,4228.74 ; PROTOTYPE1.H3@458.44,4225.91 ccw(c415.77,4268.59) 476.12,4268.59 ccw(c536.48,4268.59) PROTOTYPE1.H3@493.8,4225.91 ; PROTOTYPE1.H3@461.27,4223.08 ccw(c425.42,4258.93) 476.12,4258.93 ccw(c526.82,4258.93) PROTOTYPE1.H3@490.97,4223.08 ; PROTOTYPE1.H3@464.1,4220.26 ccw(c435.08,4249.28) 476.12,4249.28 ccw(c517.16,4249.28) PROTOTYPE1.H3@488.14,4220.26 ; PROTOTYPE1.H3@466.93,4217.43 ccw(c444.74,4239.62) 476.12,4239.62 ccw(c507.51,4239.62) PROTOTYPE1.H3@485.31,4217.43 ; PROTOTYPE1.H3@476.12,4208.23 476.12,4300.3 950.86,4775.04 1090.19,4775.04 1128.38,4813.23 ; UH1.6@1152.3,4799.45 ccw(c1128.39,4785.61) 1128.39,4813.23 ; UH1.6@1152.3,4827.02 cw(c1128.39,4840.86) 1128.39,4813.23 ; UH1.6@1155.76,4801.45 ccw(c1135.32,4789.62) 1135.32,4813.23 ccw(c1135.32,4836.84) UH1.6@1155.76,4825.02 ; UH1.6@1159.22,4803.45 ccw(c1142.26,4793.64) 1142.26,4813.23 ccw(c1142.26,4832.83) UH1.6@1159.22,4823.02 ; UH1.6@1176.12,4813.23 1128.38,4813.23 ; v1(4627.52,4308.37) 4649.15,4330 4799.31,4330 4821.2,4308.11 4855.26,4308.11 4860,4308.11 4870,4308.11 4918.62,4308.11 v3(4996.3,4308.11) ; v1@4627.52,4313.87 ccw(c4627.52,4327.15) 4636.91,4317.76 ccw(c4646.3,4308.37) v1@4633.02,4308.37 ; v1@4627.52,4317.87 ccw(c4627.52,4340.81) 4643.74,4324.59 ccw(c4659.96,4308.37) v1@4637.02,4308.37 ; v3@4991,4302.81 ccw(c4978.19,4290) 4978.19,4308.11 ccw(c4978.19,4326.22) v3@4991,4313.41 ; v3@4991.11,4302.92 ccw(c4978.57,4290.38) 4978.57,4308.11 ccw(c4978.57,4325.84) v3@4991.11,4313.3
  MidLayer2 w4: v1(-585,3645) -585,3660.52 -584.81,3660.71 -526.48,3719.04 -481,3764.52 -481,4067.02 -230.98,4317.04 -153.67,4317.04 -120,4283.37 -68.14,4283.37 -26.48,4241.71 23.52,4241.71 40.19,4258.37 425.98,4258.37 PROTOTYPE1.H3@476.12,4208.23 ; PROTOTYPE1.H3@447.12,4208.23 ccw(c377.11,4208.23) 426.62,4257.74 ccw(c476.12,4307.25) PROTOTYPE1.H3@476.12,4237.23 ; PROTOTYPE1.H3@451.12,4208.23 ccw(c390.77,4208.23) 433.44,4250.91 ccw(c476.12,4293.59) PROTOTYPE1.H3@476.12,4233.23 ; PROTOTYPE1.H3@455.12,4208.23 ccw(c404.42,4208.23) 440.27,4244.08 ccw(c476.12,4279.93) PROTOTYPE1.H3@476.12,4229.23 ; PROTOTYPE1.H3@459.12,4208.23 ccw(c418.08,4208.23) 447.1,4237.26 ccw(c476.12,4266.28) PROTOTYPE1.H3@476.12,4225.23 ; PROTOTYPE1.H3@463.12,4208.23 ccw(c431.74,4208.23) 453.93,4230.43 ccw(c476.12,4252.62) PROTOTYPE1.H3@476.12,4221.23 ; UH1.6@1176.12,4813.23 1254.59,4891.71 v1(2206.86,4891.71) ; UH1.6@1176.12,4828.76 ccw(c1176.12,4866.25) 1202.63,4839.74 ccw(c1229.14,4813.23) UH1.6@1191.65,4813.23 ; UH1.6@1176.12,4832.76 ccw(c1176.12,4879.91) 1209.46,4846.57 ccw(c1242.79,4813.23) UH1.6@1195.65,4813.23 ; UH1.6@1176.12,4836.76 ccw(c1176.12,4893.56) 1216.29,4853.4 ccw(c1256.45,4813.23) UH1.6@1199.65,4813.23 ; UH1.6@1176.12,4840.76 ccw(c1176.12,4907.22) 1223.11,4860.23 ccw(c1270.11,4813.23) UH1.6@1203.65,4813.23 ; v1@2200.14,4884.99 ccw(c2183.92,4868.77) 2183.92,4891.71 ccw(c2183.92,4914.64) v1@2200.14,4898.43 ; v1@2202.97,4887.82 ccw(c2193.58,4878.43) 2193.58,4891.71 ccw(c2193.58,4904.99) v1@2202.97,4895.6
  Bottom Layer w4: v1@2206.86,4882.21 cw(c2206.86,4859.27) 2223.07,4875.49 cw(c2239.29,4891.71) v1@2216.36,4891.71 ; v1@2206.86,4886.21 cw(c2206.86,4872.93) 2216.25,4882.32 cw(c2225.64,4891.71) v1@2212.36,4891.71 ; v1(2206.86,4891.71) 2332.25,4766.31 2403.69,4766.31 2415.19,4754.81 2415.19,4679.81 2494.96,4600.04 4238.19,4600.04 4479.86,4358.37 4497.19,4341.04 4540.8,4341.04 4573.46,4308.37 v1(4627.52,4308.37) ; v1@4620.81,4301.66 ccw(c4604.59,4285.44) 4604.59,4308.37 ccw(c4604.59,4331.31) v1@4620.81,4315.09 ; v1@4623.64,4304.49 ccw(c4614.25,4295.1) 4614.25,4308.37 ccw(c4614.25,4321.65) v1@4623.64,4312.26
ATE.UIO.IO5: J33.A16 PROTOTYPE1.H4 U8.M2 UH1.7 | length 8793.2
  Top Layer w4: J33.A16@-785.98,3597.74 -780.91,3602.81 -605.07,3602.81 -587.26,3585 v1(-415,3585) ; v1@-421.72,3578.28 ccw(c-437.94,3562.06) -437.94,3585 ccw(c-437.94,3607.93) v1@-421.72,3591.72 ; v1@-418.89,3581.11 ccw(c-428.28,3571.72) -428.28,3585 ccw(c-428.28,3598.28) v1@-418.89,3588.89 ; PROTOTYPE1.H4@555.62,4228.74 ccw(c506.11,4278.25) 576.12,4278.25 ccw(c646.13,4278.25) PROTOTYPE1.H4@596.63,4228.74 ; PROTOTYPE1.H4@558.44,4225.91 ccw(c515.77,4268.59) 576.12,4268.59 ccw(c636.48,4268.59) PROTOTYPE1.H4@593.8,4225.91 ; PROTOTYPE1.H4@561.27,4223.08 ccw(c525.42,4258.93) 576.12,4258.93 ccw(c626.82,4258.93) PROTOTYPE1.H4@590.97,4223.08 ; PROTOTYPE1.H4@564.1,4220.26 ccw(c535.08,4249.28) 576.12,4249.28 ccw(c617.16,4249.28) PROTOTYPE1.H4@588.14,4220.26 ; PROTOTYPE1.H4@566.93,4217.43 ccw(c544.74,4239.62) 576.12,4239.62 ccw(c607.51,4239.62) PROTOTYPE1.H4@585.31,4217.43 ; PROTOTYPE1.H4@576.12,4208.23 576.12,4321.12 745,4490 785,4490 828.37,4533.37 v1(931.86,4533.37) ; v1@925.14,4526.66 ccw(c908.92,4510.44) 908.92,4533.37 ccw(c908.92,4556.31) v1@925.14,4540.09 ; v1@927.97,4529.49 ccw(c918.58,4520.1) 918.58,4533.37 ccw(c918.58,4546.65) v1@927.97,4537.26 ; v1@1175.14,4465.09 ccw(c1158.92,4481.31) 1181.86,4481.31 ccw(c1204.79,4481.31) v1@1188.57,4465.09 ; v1@1177.97,4462.26 ccw(c1168.58,4471.65) 1181.86,4471.65 ccw(c1195.14,4471.65) v1@1185.75,4462.26 ; v1(1181.86,4458.37) 1181.86,4491.71 1276.12,4585.97 UH1.7@1276.12,4713.23 ; UH1.7@1256.66,4693.77 cw(c1209.66,4646.78) 1276.12,4646.78 cw(c1342.58,4646.78) UH1.7@1295.59,4693.77 ; UH1.7@1259.48,4696.6 cw(c1219.32,4656.43) 1276.12,4656.43 cw(c1332.92,4656.43) UH1.7@1292.76,4696.6 ; UH1.7@1262.31,4699.43 cw(c1228.98,4666.09) 1276.12,4666.09 cw(c1323.26,4666.09) UH1.7@1289.93,4699.43 ; UH1.7@1265.14,4702.26 cw(c1238.63,4675.75) 1276.12,4675.75 cw(c1313.61,4675.75) UH1.7@1287.1,4702.26 ; v1(4381.86,4416.71) 4442.56,4416.71 4509.23,4350.04 4550,4350.04 4575,4375.04 4658.86,4375.04 4667.19,4366.71 4667.19,4341.71 4678.86,4330.04 4678.86,4270.37 4688.19,4261.04 4726.84,4261.04 4739.17,4248.71 4763.86,4248.71 4781.02,4265.87 4814.42,4265.87 4815.73,4264.56 4855.26,4264.56 4860,4264.56 4870,4264.56 4917.53,4264.56 cw(c4917.53,4254.41) 4924.71,4261.59 ; v1@4385.75,4412.82 cw(c4395.14,4403.43) 4395.14,4416.71 cw(c4395.14,4429.99) v1@4385.75,4420.6 ; v1@4388.57,4409.99 cw(c4404.79,4393.77) 4404.79,4416.71 cw(c4404.79,4439.64) v1@4388.57,4423.43 ; U8.M2@4929.9,4249.06 ccw(c4912.17,4249.06) 4924.71,4261.59 ; U8.M2@4937.24,4256.4 cw(c4937.24,4274.12) 4924.71,4261.59
  MidLayer2 w4: v1@-415,3575.5 cw(c-415,3552.56) -398.78,3568.78 cw(c-382.57,3585) v1@-405.5,3585 ; v1@-415,3579.5 cw(c-415,3566.22) -405.61,3575.61 cw(c-396.22,3585) v1@-409.5,3585 ; v1(-415,3585) -354.23,3524.23 -90.81,3524.23 -58.04,3557 178.04,3557 185,3550.04 v1(213.86,3550.04) ; v1@207.14,3543.32 ccw(c190.92,3527.11) 190.92,3550.04 ccw(c190.92,3572.98) v1@207.14,3556.76 ; v1@209.97,3546.15 ccw(c200.58,3536.76) 200.58,3550.04 ccw(c200.58,3563.32) v1@209.97,3553.93 ; v1(1181.86,4458.37) 1403.37,4458.37 1420.37,4475.37 4273.19,4475.37 4299.49,4449.07 4349.49,4449.07 4365.19,4433.37 v1(4381.86,4416.71) ; v1@1185.75,4454.49 cw(c1195.14,4445.1) 1195.14,4458.37 cw(c1195.14,4471.65) v1@1185.75,4462.26 ; v1@1188.57,4451.66 cw(c1204.79,4435.44) 1204.79,4458.37 cw(c1204.79,4481.31) v1@1188.57,4465.09 ; v1@4372.36,4416.71 ccw(c4349.42,4416.71) 4365.64,4432.93 ccw(c4381.86,4449.14) v1@4381.86,4426.21 ; v1@4376.36,4416.71 ccw(c4363.08,4416.71) 4372.47,4426.1 ccw(c4381.86,4435.49) v1@4381.86,4422.21
  Bottom Layer w4: v1(213.86,3550.04) 315.04,3550.04 325,3560 325,4140 345,4160 527.89,4160 ; v1@217.75,3546.15 cw(c227.14,3536.76) 227.14,3550.04 cw(c227.14,3563.32) v1@217.75,3553.93 ; v1@220.57,3543.32 cw(c236.79,3527.11) 236.79,3550.04 cw(c236.79,3572.98) v1@220.57,3556.76 ; PROTOTYPE1.H4@547.13,4207.7 cw(c481.42,4206.47) 527.89,4160 ; PROTOTYPE1.H4@551.13,4207.77 cw(c494.48,4206.72) 534.54,4166.66 cw(c574.6,4126.59) PROTOTYPE1.H4@575.66,4183.24 ; PROTOTYPE1.H4@555.12,4207.84 cw(c507.54,4206.96) 541.19,4173.31 cw(c574.85,4139.66) PROTOTYPE1.H4@575.73,4187.24 ; PROTOTYPE1.H4@559.12,4207.92 cw(c520.61,4207.2) 547.85,4179.96 cw(c575.09,4152.72) PROTOTYPE1.H4@575.8,4191.24 ; PROTOTYPE1.H4@575.58,4179.24 ccw(c574.36,4113.53) 527.89,4160 ; PROTOTYPE1.H4@576.12,4208.23 527.89,4160 ; v1(931.86,4533.37) 1106.86,4533.37 v1(1181.86,4458.37) ; v1@935.75,4529.49 cw(c945.14,4520.1) 945.14,4533.37 cw(c945.14,4546.65) v1@935.75,4537.26 ; v1@938.57,4526.66 cw(c954.79,4510.44) 954.79,4533.37 cw(c954.79,4556.31) v1@938.57,4540.09 ; v1@1172.36,4458.37 ccw(c1149.42,4458.37) 1165.64,4474.59 ccw(c1181.86,4490.81) v1@1181.86,4467.87 ; v1@1176.36,4458.37 ccw(c1163.08,4458.37) 1172.47,4467.76 ccw(c1181.86,4477.15) v1@1181.86,4463.87
ATE.UIO.IO6: J33.A18 PROTOTYPE1.H5 U8.L7 UH1.8 | length 10019.8
  Top Layer w4: J33.A18@-785.98,3519 -712,3519 -695,3502 -631.69,3502 -625.31,3508.37 v1(-601.48,3508.37) ; J33.A18@-716.6,3515.25 cw(c-714.64,3500.26) J33.A18@-703.95,3510.95 ; J33.A18@-716.08,3511.29 cw(c-713.32,3490.09) -698.21,3505.21 ; J33.A18@-705.3,3519 ccw(c-689.13,3519) -700.57,3507.57 ; v1@-608.19,3501.66 ccw(c-624.41,3485.44) -624.41,3508.37 ccw(c-624.41,3531.31) v1@-608.19,3515.09 ; v1@-605.36,3504.49 ccw(c-614.75,3495.1) -614.75,3508.37 ccw(c-614.75,3521.65) v1@-605.36,3512.26 ; PROTOTYPE1.H5@655.62,4228.74 ccw(c606.11,4278.25) 676.12,4278.25 ccw(c746.13,4278.25) PROTOTYPE1.H5@696.63,4228.74 ; PROTOTYPE1.H5@658.44,4225.91 ccw(c615.77,4268.59) 676.12,4268.59 ccw(c736.48,4268.59) PROTOTYPE1.H5@693.8,4225.91 ; PROTOTYPE1.H5@661.27,4223.08 ccw(c625.42,4258.93) 676.12,4258.93 ccw(c726.82,4258.93) PROTOTYPE1.H5@690.97,4223.08 ; PROTOTYPE1.H5@664.1,4220.26 ccw(c635.08,4249.28) 676.12,4249.28 ccw(c717.16,4249.28) PROTOTYPE1.H5@688.14,4220.26 ; PROTOTYPE1.H5@666.93,4217.43 ccw(c644.74,4239.62) 676.12,4239.62 ccw(c707.51,4239.62) PROTOTYPE1.H5@685.31,4217.43 ; PROTOTYPE1.H5@676.12,4208.23 676.12,4301.12 890,4515 1113.48,4515 1155.45,4556.96 1215.19,4616.71 1215.19,4752.3 UH1.8@1276.12,4813.23 ; UH1.8@1248.59,4813.23 cw(c1182.14,4813.23) 1229.13,4766.24 cw(c1276.12,4719.25) UH1.8@1276.12,4785.71 ; UH1.8@1252.59,4813.23 cw(c1195.79,4813.23) 1235.96,4773.07 cw(c1276.12,4732.91) UH1.8@1276.12,4789.71 ; UH1.8@1256.59,4813.23 cw(c1209.45,4813.23) 1242.79,4779.9 cw(c1276.12,4746.56) UH1.8@1276.12,4793.71 ; UH1.8@1260.59,4813.23 cw(c1223.11,4813.23) 1249.61,4786.73 cw(c1276.12,4760.22) UH1.8@1276.12,4797.71 ; v3(5114.41,4308.11) U8.L7@5134.09,4288.43 ; U8.L7@5126.59,4288.43 ccw(c5108.49,4288.43) 5121.29,4301.23 ccw(c5134.09,4314.03) U8.L7@5134.09,4295.93 ; U8.L7@5126.75,4288.43 ccw(c5109.03,4288.43) 5121.56,4300.96 ccw(c5134.09,4313.49) U8.L7@5134.09,4295.77 ; 5127.21,4295.31 ccw(c5114.41,4282.5) 5114.41,4300.61 cw(c5114.41,4282.5) 5127.21,4295.31 ; 5127.21,4295.31 cw(c5140.02,4308.11) 5121.91,4308.11 ccw(c5140.02,4308.11) 5127.21,4295.31
  MidLayer1 w4: PROTOTYPE1.H5@676.12,4208.23 723.86,4160.5 723.86,3300.37 v1(698.52,3275.04) ; PROTOTYPE1.H5@676.57,4191.24 cw(c677.55,4153.69) 704.1,4180.25 cw(c730.66,4206.81) PROTOTYPE1.H5@693.12,4207.79 ; PROTOTYPE1.H5@676.67,4187.24 cw(c677.88,4140.86) 710.69,4173.67 cw(c743.49,4206.48) PROTOTYPE1.H5@697.11,4207.69 ; PROTOTYPE1.H5@676.77,4183.24 cw(c678.22,4128.03) 717.27,4167.08 cw(c756.33,4206.14) PROTOTYPE1.H5@701.11,4207.58 ; PROTOTYPE1.H5@676.88,4179.24 cw(c678.55,4115.2) 723.86,4160.5 cw(c769.16,4205.8) PROTOTYPE1.H5@705.11,4207.48 ; v1@698.52,3280.54 ccw(c698.52,3293.82) 707.91,3284.43 ccw(c717.3,3275.04) v1@704.02,3275.04 ; v1@698.52,3284.54 ccw(c698.52,3307.48) 714.74,3291.26 ccw(c730.96,3275.04) v1@708.02,3275.04 ; v1(1548.52,4850.04) 1568.48,4870 2715,4870 2731.86,4853.14 2731.86,4783.37 2748.52,4766.71 2905,4766.71 2925,4786.71 2925,4835 2967,4877 3741.39,4877 3851.69,4766.71 3948.29,4766.71 4364.96,4350.04 v1(4416.19,4350.04) ; v1@1548.52,4855.54 ccw(c1548.52,4868.82) 1557.91,4859.43 ccw(c1567.3,4850.04) v1@1554.02,4850.04 ; v1@1548.52,4859.54 ccw(c1548.52,4882.48) 1564.74,4866.26 ccw(c1580.96,4850.04) v1@1558.02,4850.04 ; v1@4409.47,4343.32 ccw(c4393.26,4327.11) 4393.26,4350.04 ccw(c4393.26,4372.98) v1@4409.47,4356.76 ; v1@4412.3,4346.15 ccw(c4402.91,4336.76) 4402.91,4350.04 ccw(c4402.91,4363.32) v1@4412.3,4353.93
  MidLayer2 w4: v1@-608.19,3501.66 cw(c-624.41,3485.44) -601.48,3485.44 cw(c-578.54,3485.44) v1@-594.76,3501.66 ; v1@-605.36,3504.49 cw(c-614.75,3495.1) -601.48,3495.1 cw(c-588.2,3495.1) v1@-597.59,3504.49 ; v1(-601.48,3508.37) -601.48,3473.33 -568.14,3440 -568.14,3211.04 -577.81,3201.37 -601.48,3201.37 -618.14,3184.71 -618.14,3108.37 -601.48,3091.71 -573.29,3091.71 -531.96,3133.04 -436.96,3133.04 -352,3218 -37,3218 -21.63,3233.37 440,3233.37 491.63,3285 575,3285 584.96,3275.04 v1(698.52,3275.04) ; v1@691.81,3268.32 ccw(c675.59,3252.11) 675.59,3275.04 ccw(c675.59,3297.98) v1@691.81,3281.76 ; v1@694.64,3271.15 ccw(c685.25,3261.76) 685.25,3275.04 ccw(c685.25,3288.32) v1@694.64,3278.93 ; UH1.8@1276.12,4813.23 1301.56,4838.67 1312.16,4838.67 1323.52,4850.04 v1(1548.52,4850.04) ; v1@1541.81,4843.32 ccw(c1525.59,4827.11) 1525.59,4850.04 ccw(c1525.59,4872.98) v1@1541.81,4856.76 ; v1@1544.64,4846.15 ccw(c1535.25,4836.76) 1535.25,4850.04 ccw(c1535.25,4863.32) v1@1544.64,4853.93 ; v1(4416.19,4350.04) 4442.17,4350.04 4483.84,4308.37 4551.5,4308.37 4590.84,4269.04 4657.86,4269.04 4708.82,4320 4743.48,4320 4748.52,4325.04 4765.19,4341.71 4810.53,4341.71 4828.62,4323.62 4860,4323.62 4870,4323.62 4997.36,4323.62 5090.9,4323.62 cw(c5090.9,4309.57) 5100.83,4319.5 ; v1@4420.08,4346.15 cw(c4429.47,4336.76) 4429.47,4350.04 cw(c4429.47,4363.32) v1@4420.08,4353.93 ; v1@4422.91,4343.32 cw(c4439.13,4327.11) 4439.13,4350.04 cw(c4439.13,4372.98) v1@4422.91,4356.76 ; v3@5106.94,4307.46 ccw(c5088.9,4305.88) 5100.54,4319.75 ccw(c5112.18,4333.62) v3@5113.76,4315.58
